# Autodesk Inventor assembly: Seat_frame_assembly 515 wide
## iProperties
Shininess: 20.0
Length Units: 11269
Angle Units: 11279
Time Units: 11290
Mass Units: 11283
Length Display Precision: 3
Angle Display Precision: 2
Created: 2001-04
Part Number: Seat_frame_assembly 515 wide
Document SubType Name: Baugruppe
Designer: dl
Density: 0.0
Volumn: 0.0
Area: 0.0
PropertySet Name: Model Information
Control State: 0
Master: False
Checked Out: False
Author: dl
